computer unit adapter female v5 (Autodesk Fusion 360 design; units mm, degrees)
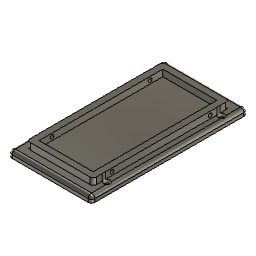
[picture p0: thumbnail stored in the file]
sketch "草图1" plane through (0, 0, 0) normal (0, 0, 1) x axis (1, 0, 0)
  line L1 (25.25, 0) -> (-25.25, 0)
  line L2 (20.25, -41.5) -> (20.25, 41.5)
  line L3 (-20.25, -41.5) -> (20.25, -41.5)
  line L4 (-20.25, 41.5) -> (-20.25, -41.5)
  line L5 (20.25, 41.5) -> (-20.25, 41.5)
  line L6 (25.25, -47.5) -> (-25.25, -47.5)
  line L7 (-25.25, 47.5) -> (25.25, 47.5)
  line L8 (-25.25, -47.5) -> (-25.25, 47.5)
  line L9 (25.25, 47.5) -> (25.25, -47.5)
  line L10 (0, -47.5) -> (0, 47.5)
  line L11 (-16.5, -37.75) -> (16.5, -37.75)
  line L12 (-16.5, 37.75) -> (-16.5, -37.75)
  line L13 (16.5, 37.75) -> (-16.5, 37.75)
  line L14 (16.5, -37.75) -> (16.5, 37.75)
  circle C1 centre (22, 35) radius 0.975
  circle C2 centre (-22, 35) radius 0.975
  circle C3 centre (-22, -35) radius 0.975
  circle C4 centre (22, -35) radius 0.975
  circle C5 centre (-22, 35) radius 1.975
  circle C6 centre (22, 35) radius 1.975
  circle C7 centre (-22, -35) radius 1.975
  circle C8 centre (22, -35) radius 1.975
  point P3 (-25.25, 0)
  point P4 (25.25, 0)
  point P6 (0, 47.5)
  point P9 (0, -47.5)
  point P19 (0, 0)
  point P10 (0, 0)
  point P8 (22, 35)
  point P11 (-22, 35)
  point P7 (22, -35)
  point P5 (25.25, 47.5)
  point P18 (25.25, -47.5)
  point P2 (-25.25, 47.5)
  point P12 (20.25, -41.5)
  point P13 (20.25, 41.5)
  point P15 (-20.25, 41.5)
  midpoint P3 L8
  midpoint P4 L9
  midpoint P6 L7
  midpoint P9 L6
  symmetric C1 C2 L10
  symmetric C1 L1 C4
  symmetric L1 C2 C3
  perpendicular L6 L8
  perpendicular L2 L5
  perpendicular L4 L5
  perpendicular L3 L4
  perpendicular L6 L9
  horizontal L7
  midpoint L1 P19
  coincident P10 P19
  dimension "d1" diameter C1 = 1.95
  dimension "d2" distance P8 P11 = 44
  dimension "d3" distance P7 P8 = 70
  dimension "d4" distance P5 P18 = 95
  dimension "d5" distance P2 P5 = 50.5
  dimension "d6" distance P12 P13 = 83
  dimension "d7" distance P13 P15 = 40.5
  dimension "d8" distance L2 L9 = 5
  dimension "d9" distance L5 L7 = 6
  dimension "d10" = 1
  dimension "d11" = 1
  dimension "d12" = 1
  dimension "d13" = 1
  dimension "d24" = 3.75 (= "4 mm - 0.25 mm")
extrude "拉伸1" new body sketch "草图1" profile of L2 L3 L4 L5 L6 L7 L8 L9 C5 C6 C7 C8 L12 L14 L13 L11 along normal blind 4
extrude "拉伸2" add sketch "草图1" profile of L2 L3 L4 L5 C5 C6 C7 C8 L12 L14 L13 L11 along normal blind 8
extrude "拉伸3" add sketch "草图1" profile of C1 C2 C3 L2 L4 C4 C5 C6 C7 C8 along normal blind 2
fillet "圆角1" radius 2
fillet "圆角2" radius 2
sketch "草图2" plane through (20.25, 0, 0) normal (1, 0, 0) x axis (0, 1, 0)
  line L1 (34.0845, 4) -> (-34.0845, 4)
  line L2 (34.0845, 8) -> (34.0845, 4)
  line L3 (-34.0845, 8) -> (34.0845, 8)
  line L4 (-34.0845, 4) -> (-34.0845, 8)
  line L5 (0, 4) -> (0, 8)
  line L6 (30, 6) -> (0, 6)
  circle C1 centre (30, 6) radius 1.125
  circle C2 centre (-30, 6) radius 1.125
  point P6 (0, 8)
  point P7 (0, 4)
  point P8 (0, 6)
  point P9 (30, 6)
  point P10 (30, 6)
  point P11 (-30, 6)
  midpoint L3 P6
  midpoint L1 P7
  midpoint L5 P8
  perpendicular L5 L6
  coincident P9 P10
  symmetric L5 C1 C2
  dimension "d25" distance P10 P11 = 60
  dimension "d26" diameter C1 = 2.25
extrude "拉伸4" cut sketch "草图2" profile of C1 C2 against normal blind 40.5
fillet "圆角3" radius 2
